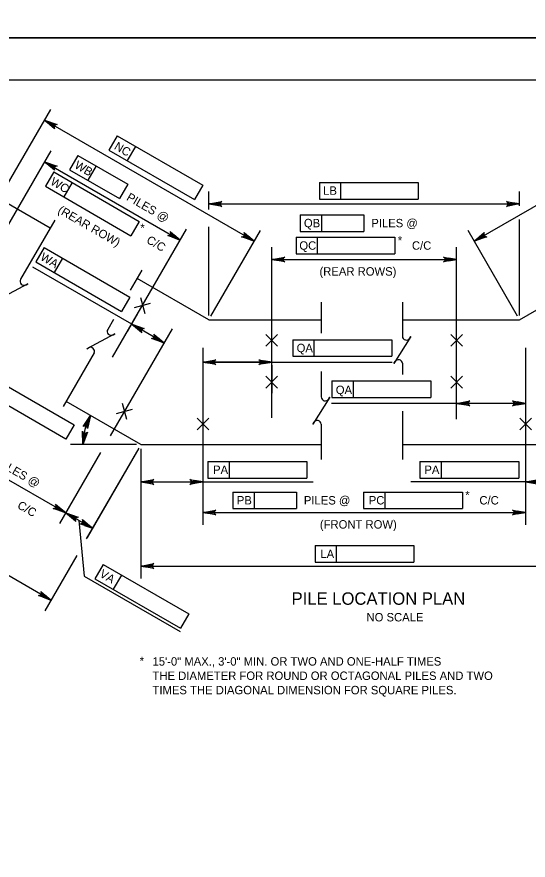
# Model space of a CAD drawing. Extents: x 638340 to 640242, y 295465 to 298435.
# Drawn here: x 639466.2 to 639648.4, y 295766.2 to 296067 of the extents above; entities that cross this region are included whole.
import ezdxf

# ---------------------------------------------------------------- set-up
doc = ezdxf.new("R2010")
doc.units = 0
for name, color, linetype in [('2', 7, 'Continuous'), ('4', 7, 'Continuous'), ('Level 2', 7, 'Continuous'), ('Level 3', 7, 'Continuous'), ('Level 4', 7, 'Continuous'), ('PLT-BNDY', 7, 'Continuous')]:
    doc.layers.add(name, color=color, linetype=linetype)

# ---------------------------------------------------------------- blocks, each defined once
blk = doc.blocks.new('PILE')
at = {"layer": '2'}
for p, q in [((-2.651625, -2.651625), (2.651625, 2.651625)), ((-2.651625, 2.651625), (2.651625, -2.651625))]:
    blk.add_line(p, q, dxfattribs=at)

msp = doc.modelspace()

# ---------------------------------------------------------------- linework, layer by layer
at = {"layer": '2'}
msp.add_line((639316.46, 296044.46), (640102.46, 296044.46), dxfattribs=at)
at = {"layer": 'Level 2'}
for p, q in [((639460.63, 296003.39), (639478.25, 296033.91)), ((639550.74, 295986.95), (639476.04, 296030.08)), ((639629.17, 295986.95), (639703.87, 296030.08)), ((639501.9, 296024.54), (639498.95, 296019.44)), ((639501.9, 296024.54), (639532.41, 296006.93)), ((639498.95, 296019.44), (639529.46, 296001.82)), ((639508.43, 296020.77), (639505.48, 296015.67)), ((639478.23, 296019.14), (639436.99, 295947.71)), ((639487.88, 296017.55), (639484.93, 296012.44)), ((639487.88, 296017.55), (639505.73, 296007.24)), ((639476.02, 296015.31), (639524.43, 295987.36)), ((639494.42, 296013.77), (639491.47, 296008.67)), ((639479.3, 296011.65), (639476.35, 296006.55)), ((639479.3, 296011.65), (639509.8, 295994.03)), ((639484.93, 296012.44), (639502.78, 296002.14)), ((639485.83, 296007.88), (639482.88, 296002.78)), ((639505.73, 296007.24), (639502.78, 296002.14)), ((639573.97, 296007.83), (639609.2, 296007.83)), ((639573.97, 296007.83), (639573.97, 296001.93)), ((639581.52, 296007.83), (639581.52, 296001.93)), ((639609.2, 296007.83), (639609.2, 296001.93)), ((639476.35, 296006.55), (639506.85, 295988.92)), ((639532.41, 296006.93), (639529.46, 296001.82)), ((639534.56, 295998.3), (639534.56, 296004.67)), ((639645.35, 295999.55), (639645.35, 296004.67)), ((639573.97, 296001.93), (639609.2, 296001.93)), ((639534.56, 296000.25), (639645.35, 296000.25)), ((639567.19, 295996.36), (639567.19, 295990.46)), ((639567.19, 295996.36), (639589.84, 295996.36)), ((639574.73, 295996.36), (639574.73, 295990.46)), ((639589.84, 295996.36), (639589.84, 295990.46)), ((639509.8, 295994.03), (639506.85, 295988.92)), ((639645.35, 295960.46), (639645.35, 295994.7)), ((639500.3, 295945.56), (639526.64, 295991.19)), ((639534.56, 295960.46), (639534.56, 295992.1)), ((639535.33, 295960.26), (639552.95, 295990.78)), ((639567.19, 295990.46), (639589.84, 295990.46)), ((639644.58, 295960.26), (639626.96, 295990.78)), ((639565.68, 295988.35), (639600.92, 295988.35)), ((639565.68, 295988.35), (639565.68, 295982.46)), ((639573.23, 295988.35), (639573.23, 295982.46)), ((639600.92, 295988.35), (639600.92, 295982.46)), ((639475.92, 295984.65), (639472.97, 295979.54)), ((639475.92, 295984.65), (639506.43, 295967.02)), ((639557.02, 295923.93), (639557.02, 295984.84)), ((639622.89, 295923.46), (639622.89, 295984.84)), ((639482.46, 295980.87), (639479.51, 295975.77)), ((639557.02, 295980.42), (639622.89, 295980.42)), ((639565.68, 295982.46), (639600.92, 295982.46)), ((639507.1, 295957.35), (639471.89, 295977.67)), ((639472.97, 295979.54), (639503.48, 295961.91)), ((639506.43, 295967.02), (639503.48, 295961.91)), ((639505.61, 295954.76), (639509.31, 295961.18)), ((639518.61, 295950.7), (639507.1, 295957.35)), ((639521.47, 295955.67), (639499.45, 295917.53)), ((639564.52, 295951.8), (639599.75, 295951.8)), ((639564.52, 295951.8), (639564.52, 295945.9)), ((639572.06, 295951.8), (639572.06, 295945.9)), ((639599.75, 295951.8), (639599.75, 295945.9)), ((639532.46, 295948.88), (639532.46, 295885.79)), ((639647.45, 295948.88), (639647.45, 295885.79)), ((639564.52, 295945.9), (639599.75, 295945.9)), ((639532.46, 295943.81), (639599.95, 295943.81)), ((639532.46, 295942.75), (639532.46, 295932.69)), ((639554.07, 295943.81), (639535.4, 295943.81)), ((639557.02, 295942.75), (639557.02, 295932.69)), ((639456.12, 295939.1), (639486.62, 295921.46)), ((639578.47, 295937.1), (639613.7, 295937.1)), ((639578.47, 295937.1), (639578.47, 295931.2)), ((639586.02, 295937.1), (639586.02, 295931.2)), ((639613.7, 295937.1), (639613.7, 295931.2)), ((639483.67, 295916.35), (639453.17, 295934)), ((639622.89, 295929.11), (639578.35, 295929.11)), ((639578.47, 295931.2), (639613.7, 295931.2)), ((639647.45, 295929.11), (639622.89, 295929.11)), ((639423.68, 295924.66), (639483.6, 295890.07)), ((639486.62, 295921.46), (639483.67, 295916.35)), ((639508.82, 295914.41), (639485.29, 295914.41)), ((639495.99, 295911.54), (639481.39, 295886.24)), ((639509.59, 295913.08), (639490.91, 295880.74)), ((639509.59, 295913.08), (639491.21, 295881.25)), ((639510.35, 295912.88), (639510.35, 295866.68)), ((639534.27, 295908.38), (639569.5, 295908.38)), ((639534.27, 295908.38), (639534.27, 295902.49)), ((639541.81, 295908.38), (639541.81, 295902.49)), ((639569.5, 295908.38), (639569.5, 295902.49)), ((639609.79, 295908.38), (639645.02, 295908.38)), ((639609.79, 295908.38), (639609.79, 295902.49)), ((639617.34, 295908.38), (639617.34, 295902.49)), ((639645.02, 295908.38), (639645.02, 295902.49)), ((639478.34, 295858.97), (639402.52, 295902.75)), ((639510.35, 295904), (639510.35, 295892.95)), ((639534.27, 295902.49), (639569.5, 295902.49)), ((639609.79, 295902.49), (639645.02, 295902.49)), ((639510.35, 295901.09), (639571.77, 295901.09)), ((639669.75, 295901.09), (639606.61, 295901.09)), ((639543.15, 295897.5), (639543.15, 295891.61)), ((639543.15, 295897.5), (639565.81, 295897.5)), ((639550.7, 295897.5), (639550.7, 295891.61)), ((639565.81, 295897.5), (639565.81, 295891.61)), ((639589.72, 295897.5), (639624.95, 295897.5)), ((639589.72, 295897.5), (639589.72, 295891.61)), ((639597.27, 295897.5), (639597.27, 295891.61)), ((639624.95, 295897.5), (639624.95, 295891.61)), ((639483.6, 295890.07), (639493.12, 295884.57)), ((639532.46, 295890.21), (639647.45, 295890.21)), ((639543.15, 295891.61), (639565.81, 295891.61)), ((639589.72, 295891.61), (639624.95, 295891.61)), ((639488.32, 295887.34), (639490.13, 295867.52)), ((639572.44, 295878.38), (639607.67, 295878.38)), ((639572.44, 295878.38), (639572.44, 295872.48)), ((639579.98, 295878.38), (639579.98, 295872.48)), ((639607.67, 295878.38), (639607.67, 295872.48)), ((639487.52, 295874.85), (639476.13, 295855.14)), ((639572.44, 295872.48), (639607.67, 295872.48)), ((639496.94, 295871.66), (639493.99, 295866.56)), ((639496.94, 295871.66), (639527.44, 295854.03)), ((639510.35, 295871.1), (639669.75, 295871.1)), ((639490.13, 295867.52), (639524.42, 295847.72)), ((639493.99, 295866.56), (639524.5, 295848.93)), ((639503.47, 295867.89), (639500.53, 295862.79)), ((639527.44, 295854.03), (639524.5, 295848.93))]:
    msp.add_line(p, q, dxfattribs=at)
for points in [[(639478.84, 296029.03), (639478.35, 296028.18), (639476.04, 296030.08)], [(639478.82, 296014.26), (639478.33, 296013.41), (639476.02, 296015.31)], [(639537.51, 296000.74), (639537.51, 295999.76), (639534.56, 296000.25)], [(639522.12, 295989.26), (639521.63, 295988.41), (639524.43, 295987.36)], [(639548.44, 295988.85), (639547.94, 295988), (639550.74, 295986.95)], [(639631.48, 295988.85), (639631.97, 295988), (639629.17, 295986.95)], [(639559.96, 295980.91), (639559.96, 295979.93), (639557.02, 295980.42)], [(639619.95, 295980.91), (639619.95, 295979.93), (639622.89, 295980.42)], [(639509.9, 295956.3), (639509.41, 295955.45), (639507.1, 295957.35)], [(639516.3, 295952.6), (639515.81, 295951.75), (639518.61, 295950.7)], [(639535.4, 295944.3), (639535.4, 295943.32), (639532.46, 295943.81)], [(639554.07, 295944.3), (639554.07, 295943.32), (639557.02, 295943.81)], [(639625.84, 295929.6), (639625.84, 295928.62), (639622.89, 295929.11)], [(639644.5, 295929.6), (639644.5, 295928.62), (639647.45, 295929.11)], [(639513.3, 295901.58), (639513.3, 295900.6), (639510.35, 295901.09)], [(639529.51, 295901.58), (639529.51, 295900.6), (639532.46, 295901.09)], [(639650.4, 295901.58), (639650.4, 295900.6), (639647.45, 295901.09)], [(639481.29, 295891.96), (639480.8, 295891.11), (639483.6, 295890.07)], [(639486.39, 295889.02), (639485.9, 295888.16), (639483.6, 295890.07)], [(639535.4, 295890.7), (639535.4, 295889.72), (639532.46, 295890.21)], [(639644.5, 295890.7), (639644.5, 295889.72), (639647.45, 295890.21)], [(639490.81, 295886.46), (639490.32, 295885.61), (639493.12, 295884.57)], [(639513.3, 295871.59), (639513.3, 295870.61), (639510.35, 295871.1)], [(639476.04, 295860.87), (639475.55, 295860.02), (639478.34, 295858.97)]]:
    msp.add_lwpolyline(points, close=True, dxfattribs=at)
for points in [[(639476.04, 296030.08), (639480.51, 296028.51), (639480.07, 296028.48), (639479.75, 296028.3), (639479.55, 296028.05), (639479.44, 296027.76), (639479.45, 296027.39), (639479.63, 296027), (639476.04, 296030.08), (639479.45, 296027.39), (639479.44, 296027.76), (639476.04, 296030.08), (639479.55, 296028.05), (639479.75, 296028.3), (639476.04, 296030.08), (639480.07, 296028.48)], [(639476.02, 296015.31), (639480.49, 296013.74), (639480.05, 296013.71), (639479.74, 296013.53), (639479.53, 296013.29), (639479.42, 296012.99), (639479.43, 296012.63), (639479.62, 296012.23), (639476.02, 296015.31), (639479.43, 296012.63), (639479.42, 296012.99), (639476.02, 296015.31), (639479.53, 296013.29), (639479.74, 296013.53), (639476.02, 296015.31), (639480.05, 296013.71)], [(639534.56, 296000.25), (639539.21, 296001.12), (639538.86, 296000.87), (639538.67, 296000.56), (639538.62, 296000.25), (639538.67, 295999.94), (639538.86, 295999.62), (639539.21, 295999.38), (639534.56, 296000.25), (639538.86, 295999.62), (639538.67, 295999.94), (639534.56, 296000.25), (639538.62, 296000.25), (639538.67, 296000.56), (639534.56, 296000.25), (639538.86, 296000.87)], [(639645.35, 296000.25), (639640.7, 295999.38), (639641.06, 295999.62), (639641.24, 295999.94), (639641.29, 296000.25), (639641.24, 296000.56), (639641.06, 296000.87), (639640.7, 296001.12), (639645.35, 296000.25), (639641.06, 296000.87), (639641.24, 296000.56), (639645.35, 296000.25), (639641.29, 296000.25), (639641.24, 295999.94), (639645.35, 296000.25), (639641.06, 295999.62)], [(639524.43, 295987.36), (639519.97, 295988.93), (639520.4, 295988.97), (639520.72, 295989.15), (639520.92, 295989.39), (639521.03, 295989.69), (639521.03, 295990.05), (639520.84, 295990.44), (639524.43, 295987.36), (639521.03, 295990.05), (639521.03, 295989.69), (639524.43, 295987.36), (639520.92, 295989.39), (639520.72, 295989.15), (639524.43, 295987.36), (639520.4, 295988.97)], [(639550.74, 295986.95), (639546.28, 295988.52), (639546.71, 295988.56), (639547.03, 295988.74), (639547.23, 295988.98), (639547.34, 295989.28), (639547.34, 295989.64), (639547.15, 295990.03), (639550.74, 295986.95), (639547.34, 295989.64), (639547.34, 295989.28), (639550.74, 295986.95), (639547.23, 295988.98), (639547.03, 295988.74), (639550.74, 295986.95), (639546.71, 295988.56)], [(639629.17, 295986.95), (639632.76, 295990.03), (639632.58, 295989.64), (639632.57, 295989.28), (639632.68, 295988.98), (639632.88, 295988.74), (639633.2, 295988.56), (639633.63, 295988.52), (639629.17, 295986.95), (639633.2, 295988.56), (639632.88, 295988.74), (639629.17, 295986.95), (639632.68, 295988.98), (639632.57, 295989.28), (639629.17, 295986.95), (639632.58, 295989.64)], [(639557.02, 295980.42), (639561.67, 295981.29), (639561.31, 295981.04), (639561.13, 295980.73), (639561.07, 295980.42), (639561.13, 295980.11), (639561.31, 295979.8), (639561.67, 295979.55), (639557.02, 295980.42), (639561.31, 295979.8), (639561.13, 295980.11), (639557.02, 295980.42), (639561.07, 295980.42), (639561.13, 295980.73), (639557.02, 295980.42), (639561.31, 295981.04)], [(639622.89, 295980.42), (639618.24, 295979.55), (639618.6, 295979.8), (639618.79, 295980.11), (639618.84, 295980.42), (639618.79, 295980.73), (639618.6, 295981.04), (639618.24, 295981.29), (639622.89, 295980.42), (639618.6, 295981.04), (639618.79, 295980.73), (639622.89, 295980.42), (639618.84, 295980.42), (639618.79, 295980.11), (639622.89, 295980.42), (639618.6, 295979.8)], [(639507.1, 295957.35), (639511.56, 295955.78), (639511.13, 295955.74), (639510.81, 295955.56), (639510.61, 295955.32), (639510.5, 295955.02), (639510.51, 295954.66), (639510.69, 295954.27), (639507.1, 295957.35), (639510.51, 295954.66), (639510.5, 295955.02), (639507.1, 295957.35), (639510.61, 295955.32), (639510.81, 295955.56), (639507.1, 295957.35), (639511.13, 295955.74)], [(639518.61, 295950.7), (639514.14, 295952.27), (639514.58, 295952.31), (639514.89, 295952.49), (639515.09, 295952.73), (639515.2, 295953.03), (639515.2, 295953.39), (639515.01, 295953.79), (639518.61, 295950.7), (639515.2, 295953.39), (639515.2, 295953.03), (639518.61, 295950.7), (639515.09, 295952.73), (639514.89, 295952.49), (639518.61, 295950.7), (639514.58, 295952.31)], [(639532.46, 295943.81), (639537.11, 295944.68), (639536.75, 295944.44), (639536.57, 295944.12), (639536.51, 295943.81), (639536.57, 295943.5), (639536.75, 295943.19), (639537.11, 295942.94), (639532.46, 295943.81), (639536.75, 295943.19), (639536.57, 295943.5), (639532.46, 295943.81), (639536.51, 295943.81), (639536.57, 295944.12), (639532.46, 295943.81), (639536.75, 295944.44)], [(639557.02, 295943.81), (639552.37, 295942.94), (639552.72, 295943.19), (639552.91, 295943.5), (639552.96, 295943.81), (639552.91, 295944.12), (639552.72, 295944.44), (639552.37, 295944.68), (639557.02, 295943.81), (639552.72, 295944.44), (639552.91, 295944.12), (639557.02, 295943.81), (639552.96, 295943.81), (639552.91, 295943.5), (639557.02, 295943.81), (639552.72, 295943.19)], [(639622.89, 295929.11), (639627.55, 295929.98), (639627.19, 295929.73), (639627, 295929.42), (639626.95, 295929.11), (639627, 295928.8), (639627.19, 295928.49), (639627.55, 295928.24), (639622.89, 295929.11), (639627.19, 295928.49), (639627, 295928.8), (639622.89, 295929.11), (639626.95, 295929.11), (639627, 295929.42), (639622.89, 295929.11), (639627.19, 295929.73)], [(639622.89, 295929.11), (639627.55, 295929.98), (639627.19, 295929.73), (639627, 295929.42), (639626.95, 295929.11), (639627, 295928.8), (639627.19, 295928.49), (639627.55, 295928.24), (639622.89, 295929.11), (639627.19, 295928.49), (639627, 295928.8), (639622.89, 295929.11), (639626.95, 295929.11), (639627, 295929.42), (639622.89, 295929.11), (639627.19, 295929.73)], [(639647.45, 295929.11), (639642.8, 295928.24), (639643.16, 295928.49), (639643.34, 295928.8), (639643.4, 295929.11), (639643.34, 295929.42), (639643.16, 295929.73), (639642.8, 295929.98), (639647.45, 295929.11), (639643.16, 295929.73), (639643.34, 295929.42), (639647.45, 295929.11), (639643.4, 295929.11), (639643.34, 295928.8), (639647.45, 295929.11), (639643.16, 295928.49)], [(639492.48, 295924.74), (639491.41, 295920.13), (639491.32, 295920.55), (639491.11, 295920.85), (639490.85, 295921.02), (639490.54, 295921.1), (639490.18, 295921.06), (639489.81, 295920.83), (639492.48, 295924.74), (639490.18, 295921.06), (639490.54, 295921.1), (639492.48, 295924.74), (639490.85, 295921.02), (639491.11, 295920.85), (639492.48, 295924.74), (639491.32, 295920.55)], [(639489.69, 295914.42), (639489.57, 295919.15), (639489.76, 295918.75), (639490.04, 295918.52), (639490.34, 295918.42), (639490.65, 295918.42), (639490.99, 295918.56), (639491.3, 295918.87), (639489.69, 295914.42), (639490.99, 295918.56), (639490.65, 295918.42), (639489.69, 295914.42), (639490.34, 295918.42), (639490.04, 295918.52), (639489.69, 295914.42), (639489.76, 295918.75)], [(639510.35, 295901.09), (639515.01, 295901.96), (639514.65, 295901.72), (639514.46, 295901.4), (639514.41, 295901.09), (639514.46, 295900.78), (639514.65, 295900.47), (639515.01, 295900.22), (639510.35, 295901.09), (639514.65, 295900.47), (639514.46, 295900.78), (639510.35, 295901.09), (639514.41, 295901.09), (639514.46, 295901.4), (639510.35, 295901.09), (639514.65, 295901.72)], [(639532.46, 295901.09), (639527.81, 295900.22), (639528.16, 295900.47), (639528.35, 295900.78), (639528.4, 295901.09), (639528.35, 295901.4), (639528.16, 295901.72), (639527.81, 295901.96), (639532.46, 295901.09), (639528.16, 295901.72), (639528.35, 295901.4), (639532.46, 295901.09), (639528.4, 295901.09), (639528.35, 295900.78), (639532.46, 295901.09), (639528.16, 295900.47)], [(639647.45, 295901.09), (639652.1, 295901.96), (639651.75, 295901.72), (639651.56, 295901.4), (639651.51, 295901.09), (639651.56, 295900.78), (639651.75, 295900.47), (639652.1, 295900.22), (639647.45, 295901.09), (639651.75, 295900.47), (639651.56, 295900.78), (639647.45, 295901.09), (639651.51, 295901.09), (639651.56, 295901.4), (639647.45, 295901.09), (639651.75, 295901.72)], [(639483.6, 295890.07), (639479.13, 295891.64), (639479.57, 295891.67), (639479.88, 295891.85), (639480.09, 295892.09), (639480.2, 295892.39), (639480.19, 295892.75), (639480, 295893.15), (639483.6, 295890.07), (639480.19, 295892.75), (639480.2, 295892.39), (639483.6, 295890.07), (639480.09, 295892.09), (639479.88, 295891.85), (639483.6, 295890.07), (639479.57, 295891.67)], [(639483.6, 295890.07), (639488.06, 295888.5), (639487.63, 295888.46), (639487.31, 295888.28), (639487.11, 295888.04), (639487, 295887.74), (639487, 295887.38), (639487.19, 295886.98), (639483.6, 295890.07), (639487, 295887.38), (639487, 295887.74), (639483.6, 295890.07), (639487.11, 295888.04), (639487.31, 295888.28), (639483.6, 295890.07), (639487.63, 295888.46)], [(639532.46, 295890.21), (639537.11, 295891.08), (639536.75, 295890.84), (639536.57, 295890.52), (639536.51, 295890.21), (639536.57, 295889.9), (639536.75, 295889.59), (639537.11, 295889.34), (639532.46, 295890.21), (639536.75, 295889.59), (639536.57, 295889.9), (639532.46, 295890.21), (639536.51, 295890.21), (639536.57, 295890.52), (639532.46, 295890.21), (639536.75, 295890.84)], [(639647.45, 295890.21), (639642.8, 295889.34), (639643.16, 295889.59), (639643.34, 295889.9), (639643.4, 295890.21), (639643.34, 295890.52), (639643.16, 295890.84), (639642.8, 295891.08), (639647.45, 295890.21), (639643.16, 295890.84), (639643.34, 295890.52), (639647.45, 295890.21), (639643.4, 295890.21), (639643.34, 295889.9), (639647.45, 295890.21), (639643.16, 295889.59)], [(639493.12, 295884.57), (639488.66, 295886.14), (639489.09, 295886.17), (639489.41, 295886.35), (639489.61, 295886.59), (639489.72, 295886.89), (639489.72, 295887.25), (639489.53, 295887.65), (639493.12, 295884.57), (639489.72, 295887.25), (639489.72, 295886.89), (639493.12, 295884.57), (639489.61, 295886.59), (639489.41, 295886.35), (639493.12, 295884.57), (639489.09, 295886.17)], [(639510.35, 295871.1), (639515.01, 295871.97), (639514.65, 295871.73), (639514.46, 295871.41), (639514.41, 295871.1), (639514.46, 295870.79), (639514.65, 295870.48), (639515.01, 295870.23), (639510.35, 295871.1), (639514.65, 295870.48), (639514.46, 295870.79), (639510.35, 295871.1), (639514.41, 295871.1), (639514.46, 295871.41), (639510.35, 295871.1), (639514.65, 295871.73)], [(639478.34, 295858.97), (639473.88, 295860.54), (639474.32, 295860.58), (639474.63, 295860.75), (639474.83, 295861), (639474.94, 295861.29), (639474.94, 295861.65), (639474.75, 295862.05), (639478.34, 295858.97), (639474.94, 295861.65), (639474.94, 295861.29), (639478.34, 295858.97), (639474.83, 295861), (639474.63, 295860.75), (639478.34, 295858.97), (639474.32, 295860.58)]]:
    msp.add_lwpolyline(points, dxfattribs=at)
msp.add_arc((639510.36, 295914.41), 20.64, 149.9993, 179.9986, dxfattribs=at)
at = {"layer": 'Level 3'}
for p, q in [((639478.02, 295991.57), (639459.86, 296002.06)), ((639534.56, 295958.93), (639509.04, 295973.66)), ((639645.35, 295958.93), (639670.87, 295973.66)), ((639534.56, 295958.93), (639574.65, 295958.93)), ((639603.57, 295958.93), (639645.35, 295958.93)), ((639510.35, 295914.41), (639483.71, 295929.8)), ((639510.35, 295914.41), (639574.65, 295914.41)), ((639603.57, 295914.41), (639669.56, 295914.41))]:
    msp.add_line(p, q, dxfattribs=at)
at = {"layer": 'Level 4'}
for p, q in [((639479.67, 295994.43), (639467.51, 295973.36)), ((639510.72, 295976.57), (639506.61, 295969.44)), ((639574.65, 295965.18), (639574.65, 295954.16)), ((639603.57, 295965.18), (639603.57, 295953.09)), ((639500.61, 295959.05), (639498.55, 295955.5)), ((639493.71, 295947.1), (639482.67, 295927.99)), ((639603.57, 295943.4), (639603.57, 295939.46)), ((639574.65, 295940.47), (639574.65, 295931.44)), ((639603.57, 295926.29), (639603.57, 295909.09)), ((639574.65, 295921.74), (639574.65, 295909.09))]:
    msp.add_line(p, q, dxfattribs=at)
for points in [[(639469.44, 295971.42), (639470.06, 295971.76), (639460.04, 295966.45), (639460.71, 295966.81)], [(639500.49, 295953.56), (639501.11, 295953.89), (639491.08, 295948.59), (639491.75, 295948.95)], [(639606.22, 295952.38), (639606.59, 295952.98), (639600.55, 295943.38), (639600.96, 295944.02)], [(639577.3, 295930.73), (639577.67, 295931.33), (639571.64, 295921.72), (639572.04, 295922.36)]]:
    msp.add_lwpolyline(points, dxfattribs=at)
for centre, start, end in [((639468.73, 295972.65), 150, 300), ((639499.78, 295954.79), 150, 300), ((639604.99, 295953.09), 180, 330), ((639492.42, 295947.69), 335.3286, 117.8672), ((639602.16, 295943.26), 5.3286, 147.8672), ((639576.07, 295931.44), 180, 330), ((639573.24, 295921.61), 5.3286, 147.8672)]:
    msp.add_arc(centre, 1.42, start, end, dxfattribs=at)
at = {"layer": 'PLT-BNDY'}
for points in [[(639276.46, 296653.46), (640117.46, 296653.46), (640117.46, 296059.46), (639276.46, 296059.46)], [(639276.46, 296059.46), (640117.46, 296059.46), (640117.46, 295465.46), (639276.46, 295465.46)]]:
    msp.add_lwpolyline(points, close=True, dxfattribs=at)

# ---------------------------------------------------------------- block references
at = {"layer": 'Level 2', "xscale": 0.7859001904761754, "yscale": 0.7859001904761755, "rotation": -30.00000000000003}
for p in [(639510.97, 295964.04), (639504.52, 295926.29)]:
    msp.add_blockref('PILE', p, dxfattribs=at)
at = {"layer": 'Level 2', "xscale": 0.7859001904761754, "yscale": 0.7859001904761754}
for p in [(639557.02, 295951.56), (639622.9, 295951.56), (639557.02, 295936.67), (639622.9, 295936.67), (639532.46, 295921.78), (639647.46, 295921.78)]:
    msp.add_blockref('PILE', p, dxfattribs=at)

# ---------------------------------------------------------------- texts
at = {"layer": '2'}
msp.add_text('NO SCALE', height=3, dxfattribs=at).set_placement((639590.78, 295851.34))
at = {"layer": '4'}
msp.add_text('PILE LOCATION PLAN', height=4.4294, dxfattribs=at).set_placement((639564.08, 295857.28))
at = {"layer": 'Level 2'}
for s, rotation, p in [('NC', 329.9382, (639500.6, 296019.94)), ('WB', 329.9382, (639486.47, 296013.23)), ('WC', 329.9382, (639477.88, 296007.34)), ('PILES @', 330, (639504.99, 296001.79)), ('LB', 359.9382, (639575.34, 296003.5)), ('(REAR ROW)', 330, (639480.52, 295997.23)), ('*', 359.9382, (639510.18, 295990.2)), ('QB', 359.9382, (639568.47, 295991.91)), ('PILES @', 359.9382, (639592.49, 295991.91)), ('C/C', 329.9382, (639512.08, 295986.54)), ('QC', 359.9382, (639566.85, 295983.91)), ('*', 359.9382, (639601.93, 295985.76)), ('C/C', 359.9382, (639606.97, 295983.91)), ('WA', 329.9382, (639474.28, 295980.46)), ('QA', 359.9382, (639565.88, 295947.36)), ('QA', 359.9382, (639579.83, 295932.43)), ('PILES @', 330, (639458.99, 295907.18)), ('PA', 359.9382, (639536.1, 295903.94)), ('PA', 359.9382, (639611.4, 295903.94)), ('PB', 359.9382, (639544.57, 295893.06)), ('PILES @', 359.9382, (639568.46, 295893.05)), ('PC', 359.9382, (639591.58, 295893.06)), ('*', 359.9382, (639625.97, 295894.91)), ('C/C', 359.9382, (639631.01, 295893.05)), ('C/C', 329.9382, (639466.07, 295891.93)), ('LA', 359.9382, (639574.34, 295873.93)), ('VA', 329.9382, (639495.37, 295867.44)), ('*', 359.9382, (639509.94, 295835.77))]:
    msp.add_text(s, height=3, rotation=rotation, dxfattribs=at).set_placement(p)
for s, p in [('(REAR ROWS)', (639574.02, 295974.67)), ('(FRONT ROW)', (639574.16, 295884.45)), ('15\'-0" MAX., 3\'-0" MIN. OR TWO AND ONE-HALF TIMES', (639514.53, 295835.58)), ('THE DIAMETER FOR ROUND OR OCTAGONAL PILES AND TWO', (639514.53, 295830.47)), ('TIMES THE DIAGONAL DIMENSION FOR SQUARE PILES.', (639514.53, 295825.35))]:
    msp.add_text(s, height=3.0001, dxfattribs=at).set_placement(p)

doc.saveas('drawing.dxf')
